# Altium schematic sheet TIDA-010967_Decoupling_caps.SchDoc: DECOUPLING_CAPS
size 431 x 279 mm; Date: Not shown in title block; ApprovedBy: Not shown in title block; CheckedBy: Not shown in title block; Author: Not shown in title block; CompanyName: Not shown in title block; DrawnBy: Justin Yin; Engineer: Not shown in title block; Organization: Not shown in title block; Address1: Not shown in title block; Address2: Not shown in title block; Address3: Not shown in title block; Address4: Not shown in title block; DocumentNumber: 6; Revision: Use project parameter SCH_Rev; SheetNumber: 6; SheetTotal: 8; PageSetup: Record=PageOptions¦CenterHorizontal=True¦CenterVertical=True¦PrintScale=1.00¦XCorrection=1.00¦YCorrection=1.00¦PrintKind=0¦BorderSize=5000000¦LeftOffset=0¦BottomOffset=0¦Orientation=2¦PaperLength=1000¦PaperWidth=1000¦Scale=100¦PaperSource=15¦PrintQuality=600¦MediaType=1¦DitherType=10¦PaperKind=Letter¦PrintScaleMode=1
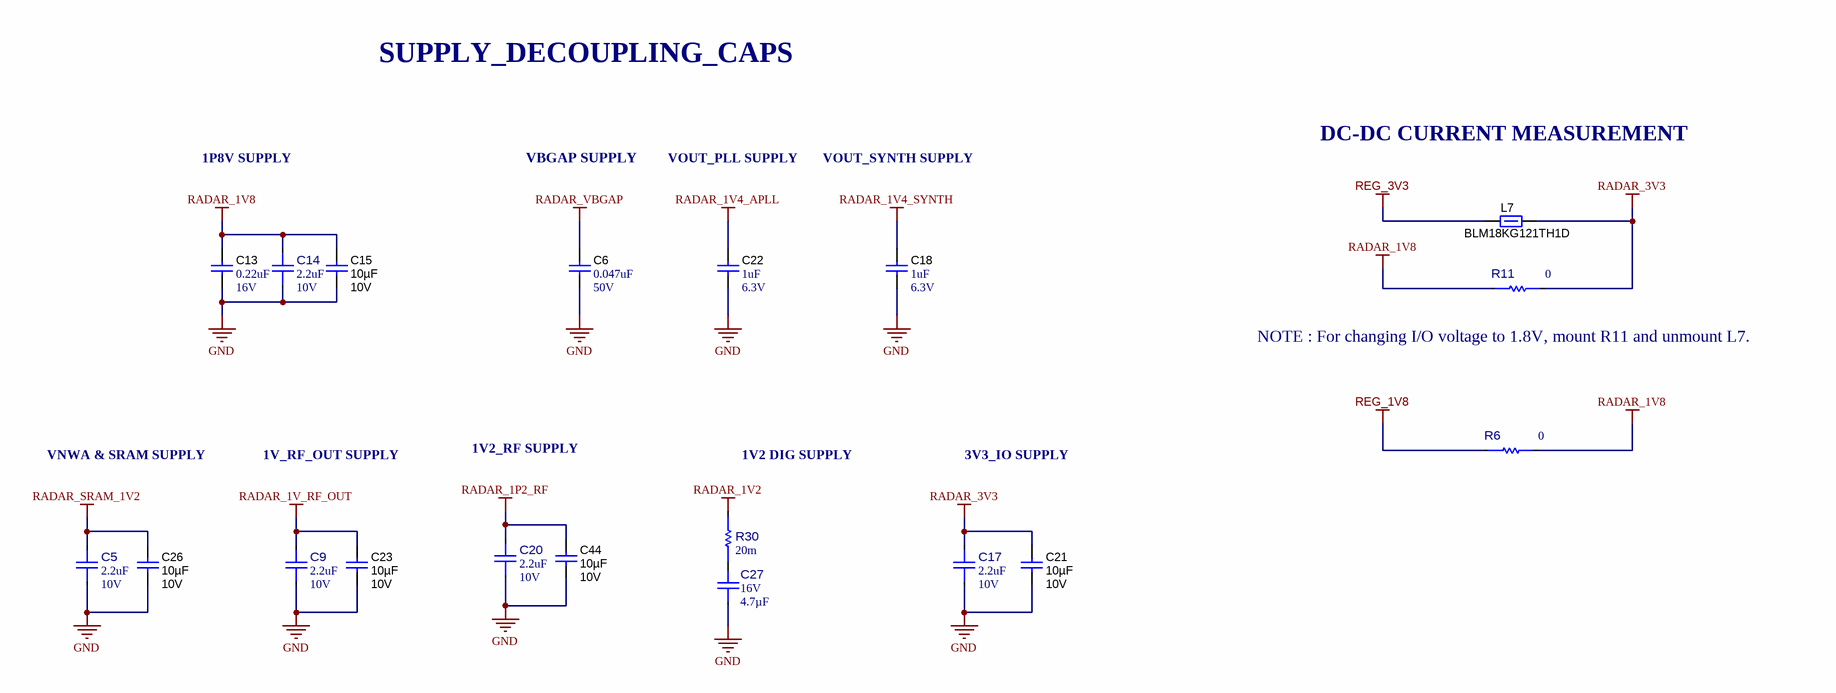
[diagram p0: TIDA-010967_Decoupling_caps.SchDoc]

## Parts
C5  ValueDisplayed: 2.2uF  VDC_V: 10V  [FP-GRM155R61A225ME01D_0402-MFG]  (hidden comment: GRM155R61A225ME01D)
C6  VDC_V: 50V  ValueDisplayed: 0.047uF  [0402L]  (hidden comment: C1005X7R1H473K050BB)
C9  ValueDisplayed: 2.2uF  VDC_V: 10V  [FP-GRM155R61A225ME01D_0402-MFG]  (hidden comment: GRM155R61A225ME01D)
C13  VDC_V: 16V  ValueDisplayed: 0.22uF  [0402L]  (hidden comment: GRM155R71C224KA12D)
C14  ValueDisplayed: 2.2uF  VDC_V: 10V  [FP-GRM155R61A225ME01D_0402-MFG]  (hidden comment: GRM155R61A225ME01D)
C15  Value2: 10V  Cap_F: 10µF  [0603L]  (hidden comment: GRM188Z71A106MA73D)
C17  ValueDisplayed: 2.2uF  VDC_V: 10V  [FP-GRM155R61A225ME01D_0402-MFG]  (hidden comment: GRM155R61A225ME01D)
C18  VDC_V: 6.3V  ValueDisplayed: 1uF  [0402S]  (hidden comment: GRM155R70J105KA12D)
C20  ValueDisplayed: 2.2uF  VDC_V: 10V  [FP-GRM155R61A225ME01D_0402-MFG]  (hidden comment: GRM155R61A225ME01D)
C21  Value2: 10V  Cap_F: 10µF  [0603L]  (hidden comment: GRM188Z71A106MA73D)
C22  VDC_V: 6.3V  ValueDisplayed: 1uF  [0402S]  (hidden comment: GRM155R70J105KA12D)
C23  Value2: 10V  Cap_F: 10µF  [0603L]  (hidden comment: GRM188Z71A106MA73D)
C26  Value2: 10V  Cap_F: 10µF  [0603L]  (hidden comment: GRM188Z71A106MA73D)
C27  VDC_V: 16V  Cap_F: 4.7µF  [FP-GCJ21BR71C475KA01L_0805-MFG]  (hidden comment: GCJ21BR71C475KA01L)
C44  Value2: 10V  Cap_F: 10µF  [0603L]  (hidden comment: GRM188Z71A106MA73D)
L7  BLM18KG121TH1D  [0603L]
R6  Res_ohm: 0  [FP-ERJ-3GEY0R00V_0603-MFG]  (hidden comment: ERJ-3GEY0R00V)
R11  Res_ohm: 0  [FP-ERJ-3GEY0R00V_0603-MFG]  (hidden comment: ERJ-3GEY0R00V)
R30  value 20m  [FP-PE0402JRF070R02L_0402-MFG]  (hidden comment: PE0402JRF070R02L)

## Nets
GND: C5.1 C6.2 C9.1 C13.2 C14.1 C15.2 C17.1 C18.2 C20.1 C21.2 C22.2 C23.2 C26.2 C27.1 C44.2
RADAR_1P2_RF: C20.2 C44.1
RADAR_1V2: R30.2
RADAR_1V4_APLL: C22.1
RADAR_1V4_SYNTH: C18.1
RADAR_1V8: C13.1 C14.2 C15.1 R6.2 R11.1
RADAR_1V_RF_OUT: C9.2 C23.1
RADAR_3V3: C17.2 C21.1 L7.2 R11.2
RADAR_SRAM_1V2: C5.2 C26.1
RADAR_VBGAP: C6.1
REG_1V8: R6.1
REG_3V3: L7.1
NetC27_2: C27.2 R30.1

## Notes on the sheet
- SUPPLY_DECOUPLING_CAPS
- DC-DC CURRENT MEASUREMENT
- 1P8V SUPPLY
- VBGAP SUPPLY
- VOUT_PLL SUPPLY
- VOUT_SYNTH SUPPLY
- (near R11) NOTE : For changing I/O voltage to 1.8V, mount R11 and unmount L7.
- VNWA & SRAM SUPPLY
- 1V_RF_OUT SUPPLY
- 1V2_RF SUPPLY
- 1V2 DIG SUPPLY
- 3V3_IO SUPPLY

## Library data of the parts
C5 C9 C14 C17 C20 = CMP-0097887-1: Chip Multilayer Ceramic Capacitors for General Purpose, 0402, 2.2uF, X5R, 15%, 20%, 10V; Manufacturer: Murata; SizeZ_mm: 0.55mm; Value: 2.2µF; AEC Qualified: No
C6 = CMP-0006298-2: CAP, CERM, 0.047 uF, 50 V, +/- 10%, X7R, 0402; Manufacturer: TDK; TaMin_C: -55°C; ESR_ohm: 0.06407; Polarized: N; SizeAreaWB_mm2: 3; Value1: 0.06407 ohm; U/M: EA; SizeZ_mm: 0.6; SizeX_mm: 1; SizeY_mm: 0.5; Cap_Case: 0402; Cap_F: 47nF; IRMS_A: 6.46122dA; AEC Category: Q200; TaMax_C: 125°C
C13 = CMP-0006648-2: CAP, CERM, 0.22 uF, 16 V, +/- 10%, X7R, 0402; Manufacturer: MuRata; TaMin_C: -55°C; Polarized: N; SizeAreaWB_mm2: 3; Value1: Unknown; U/M: EA; Value: 0.22uF; TaMax_C: 125°C; SizeZ_mm: 0.6; SizeX_mm: 1; SizeY_mm: 0.5; Cap_Case: 0402; Cap_F: 220nF; AEC Category: Q200
C15 C21 C23 C26 C44 = CMP-0007497-5: CAP, CERM, 10 uF, 10 V, +/- 20%, X7R, 0603; Manufacturer: MuRata; TaMin_C: -55°C; Polarized: N; SizeAreaWB_mm2: 4.68; Value1: Unknown; U/M: EA; Value: 10uF; TaMax_C: 125°C; SizeZ_mm: 1; SizeX_mm: 1.6; SizeY_mm: 0.8; Cap_Case: 0603; SizeArea_mm2: 1.28; AEC Category: Q200
C18 C22 = CMP-0064947-2: CAP, CERM, 1 uF, 6.3 V,+/- 10%, X7R, 0402; Manufacturer: MuRata; TaMin_C: -55°C; Polarized: N; SizeAreaWB_mm2: 3; Value1: Unknown; U/M: EA; Value: 1uF; TaMax_C: 125°C; SizeZ_mm: 0.6; SizeX_mm: 1; SizeY_mm: 0.5; Cap_Case: 0402; Cap_F: 1µF; AEC Category: Q200
C27 = CMP-0094778-1: Multilayer Ceramic Capacitors MLCC - SMD/SMT 0805 4.7uF 10%, 16VDC,  X7R 15%; Manufacturer: Murata; AEC Qualified: Yes; Value: 4.7µF; AEC Grade: Grade 1; SizeZ_mm: 1.45mm
L7 = CMP-0077879-2: Ferrite Bead, 120 ohm @ 100 MHz, 1.9 A, 0603; Manufacturer: MuRata; ZTyp@100MHz_Ohm: 120; SizeAreaWB_mm2: 4.68; DCR_ohm: 0.04; Value1: 0.04 ohm; Value: 120 ohm; Imax_A: 1.9A; SizeZ_mm: 1.0; SizeX_mm: 1.6; SizeY_mm: 0.8; SizeArea_mm2: 1.28
R6 R11 = CMP-0089143-1: 0 Ohms Jumper 0.1W, 1/10W Chip Resistor 0603 (1608 Metric) Automotive AEC-Q200 Thick Film; Manufacturer: Panasonic; SizeZ_mm: 0.55mm; AEC Grade: Grade 0; VDC_V: 75V; TempCo: -100/+600ppm/°C; AEC Qualified: Yes; Power_W: 100mW; Tolerance_%: 5%
R30 = CMP-0094620-1: Resistor Current Sense Metal Film 0402 20mOhm ±5% 1/16W ±350ppm/°C Paper T/R Automotive; Manufacturer: Yageo; AEC Qualified: Yes; Power_W: 63mW; TempCo: 100ppm/°C; SizeZ_mm: 0.5mm; AEC Grade: Grade 1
